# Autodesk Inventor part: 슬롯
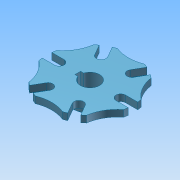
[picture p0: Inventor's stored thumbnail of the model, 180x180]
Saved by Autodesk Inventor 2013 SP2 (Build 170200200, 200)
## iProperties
Created: 2025-09
Part Number: 슬롯
Material: Generic
Document SubType Name: Modeling
Designer: a
Density: 1 g/cm^3
Author: a
변환 표준: STEP AP214IS
전처리기: Build: 200, Release: 2013 SP2 Update 6 - Date: Thu 07/17/2014
전송 단위: 밀리미터
불확실성: 0.01
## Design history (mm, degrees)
node "슬롯1"
node "솔리드1"
node "기준1"
